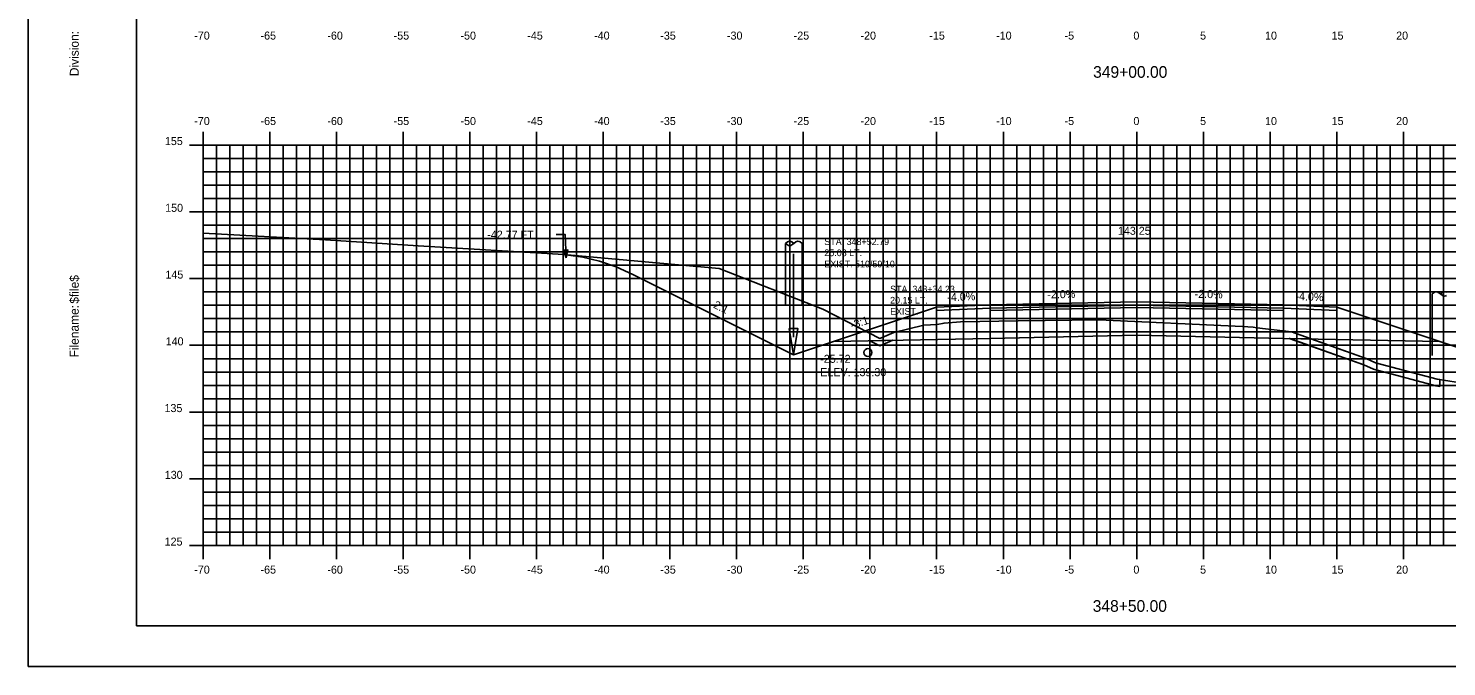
# Model space of a CAD drawing. Extents: x 1144307 to 1144477, y 608981 to 609091.
# Drawn here: x 1144307 to 1144413.3, y 608981.3 to 609029.1 of the extents above; entities that cross this region are included whole.
import ezdxf

# ---------------------------------------------------------------- set-up
doc = ezdxf.new("R2010")
doc.units = 0
for name, color, linetype in [('ANNOTATION', 7, 'Continuous'), ('BORDER', 7, 'Continuous'), ('D_Drainage_Ditch_Line', 7, 'Continuous'), ('D_Roadway_Centerline', 7, 'Continuous'), ('D_Roadway_Centerline_Text', 7, 'Continuous'), ('D_Roadway_Edge_Shoulder', 7, 'Continuous'), ('D_Roadway_Edge_TW', 7, 'Continuous'), ('D_Roadway_Pavement', 7, 'Continuous'), ('D_Roadway_SlopeLines', 7, 'Continuous'), ('D_Roadway_SubGrade', 7, 'Continuous'), ('D_Text_Monospaced', 7, 'Continuous'), ('D_Text_Standard', 7, 'Continuous'), ('H_V ANNOTATION', 7, 'Continuous'), ('MAJOR', 7, 'Continuous'), ('MINOR', 7, 'Continuous'), ('PLOT BOUNDARY', 7, 'Continuous'), ('S_Drainage_Invert', 7, 'Continuous'), ('S_Roadway_Centerline', 7, 'Continuous'), ('S_Utilities_Pole_Power', 7, 'Continuous'), ('SHADING', 7, 'Continuous')]:
    doc.layers.add(name, color=color, linetype=linetype)

msp = doc.modelspace()

# ---------------------------------------------------------------- linework, layer by layer
msp.add_lwpolyline([(1144347.33, 609012.13), (1144348.58, 609011.95), (1144349.83, 609011.65), (1144351.08, 609011.22), (1144352.33, 609010.65), (1144364.38, 609004.63), (1144367.38, 609005.63), (1144375.1, 609008.2), (1144375.11, 609008.2), (1144379.11, 609008.37), (1144390.11, 609008.59), (1144401.11, 609008.37), (1144405.11, 609008.2), (1144412.83, 609005.63), (1144415.83, 609004.63), (1144425.95, 609001.26)])
at = {"layer": 'BORDER'}
msp.add_lwpolyline([(1144315.11, 608984.34), (1144475.11, 608984.34), (1144475.11, 609089.34), (1144315.11, 609089.34)], close=True, dxfattribs=at)
at = {"layer": 'D_Drainage_Ditch_Line'}
msp.add_line((1144364.38, 609005.94), (1144364.38, 609012.19), dxfattribs=at)
msp.add_lwpolyline([(1144364.05, 609006.6), (1144364.71, 609006.6), (1144364.38, 609004.63)], close=True, dxfattribs=at)
at = {"layer": 'D_Roadway_Edge_Shoulder'}
for points in [[(1144379.11, 609008.37), (1144375.11, 609008.2), (1144375.11, 609007.96), (1144379.11, 609008.12)], [(1144401.11, 609008.37), (1144405.11, 609008.2), (1144405.11, 609007.96), (1144401.11, 609008.12)]]:
    msp.add_lwpolyline(points, close=True, dxfattribs=at)
at = {"layer": 'D_Roadway_Edge_TW'}
msp.add_lwpolyline([(1144379.11, 609008.12), (1144379.11, 609008.37), (1144390.11, 609008.59), (1144401.11, 609008.37), (1144401.11, 609008.12), (1144390.11, 609008.34)], close=True, dxfattribs=at)
at = {"layer": 'D_Roadway_Pavement'}
msp.add_lwpolyline([(1144379.11, 609007.95), (1144379.11, 609008.12), (1144390.11, 609008.34), (1144401.11, 609008.12), (1144401.11, 609007.95), (1144390.11, 609008.17)], close=True, dxfattribs=at)
at = {"layer": 'D_Roadway_SlopeLines'}
for points in [[(1144364.38, 609004.63), (1144352.33, 609010.65), (1144351.08, 609011.22), (1144349.83, 609011.65), (1144348.58, 609011.95), (1144347.33, 609012.13)], [(1144367.38, 609005.63), (1144364.38, 609004.63)], [(1144412.83, 609005.63), (1144415.83, 609004.63)]]:
    msp.add_lwpolyline(points, dxfattribs=at)
at = {"layer": 'D_Roadway_SubGrade'}
msp.add_line((1144412.83, 609002.77), (1144412.83, 609002.26), dxfattribs=at)
for points in [[(1144379.11, 609007.95), (1144379.11, 609008.12), (1144375.11, 609007.96), (1144375.11, 609008.2), (1144375.1, 609008.2), (1144367.38, 609005.63), (1144379.11, 609005.86)], [(1144379.11, 609005.86), (1144379.11, 609007.95), (1144390.11, 609008.17), (1144401.11, 609007.95), (1144401.11, 609005.86), (1144390.11, 609006.09)], [(1144401.11, 609007.95), (1144401.11, 609008.12), (1144405.11, 609007.96), (1144405.11, 609008.2), (1144405.11, 609008.2), (1144412.83, 609005.63), (1144401.11, 609005.86)]]:
    msp.add_lwpolyline(points, close=True, dxfattribs=at)
for points in [[(1144370.1, 609005.68), (1144370.84, 609005.31), (1144371.83, 609005.72)], [(1144401.55, 609005.86), (1144401.6, 609005.85), (1144407.13, 609003.89), (1144407.85, 609003.55), (1144412.54, 609002.31), (1144412.83, 609002.26)], [(1144401.55, 609005.86), (1144401.6, 609005.85), (1144407.13, 609003.89), (1144407.85, 609003.55), (1144412.54, 609002.31), (1144412.83, 609002.26)]]:
    msp.add_lwpolyline(points, dxfattribs=at)
at = {"layer": 'D_Text_Standard'}
msp.add_lwpolyline([(1144347.33, 609011.9), (1144347.27, 609013.63), (1144346.59, 609013.63)], dxfattribs=at)
msp.add_lwpolyline([(1144347.33, 609011.9), (1144347.17, 609012.48), (1144347.46, 609012.49)], close=True, dxfattribs=at)
at = {"layer": 'MAJOR'}
for p, q in [((1144320.11, 609021.34), (1144320.11, 609020.34)), ((1144325.11, 609021.34), (1144325.11, 609020.34)), ((1144330.11, 609021.34), (1144330.11, 609020.34)), ((1144335.11, 609021.34), (1144335.11, 609020.34)), ((1144340.11, 609021.34), (1144340.11, 609020.34)), ((1144345.11, 609021.34), (1144345.11, 609020.34)), ((1144350.11, 609021.34), (1144350.11, 609020.34)), ((1144355.11, 609021.34), (1144355.11, 609020.34)), ((1144360.11, 609021.34), (1144360.11, 609020.34)), ((1144365.11, 609021.34), (1144365.11, 609020.34)), ((1144370.11, 609021.34), (1144370.11, 609020.34)), ((1144375.11, 609021.34), (1144375.11, 609020.34)), ((1144380.11, 609021.34), (1144380.11, 609020.34)), ((1144385.11, 609021.34), (1144385.11, 609020.34)), ((1144390.11, 609021.34), (1144390.11, 609020.34)), ((1144395.11, 609021.34), (1144395.11, 609020.34)), ((1144400.11, 609021.34), (1144400.11, 609020.34)), ((1144405.11, 609021.34), (1144405.11, 609020.34)), ((1144410.11, 609021.34), (1144410.11, 609020.34)), ((1144319.1, 609020.34), (1144320.11, 609020.34)), ((1144320.11, 609020.34), (1144460.11, 609020.34)), ((1144320.11, 608990.34), (1144320.11, 609020.34)), ((1144320.11, 608990.34), (1144320.11, 609020.34)), ((1144320.11, 609020.34), (1144460.11, 609020.34)), ((1144325.11, 608990.34), (1144325.11, 609020.34)), ((1144330.11, 608990.34), (1144330.11, 609020.34)), ((1144335.11, 608990.34), (1144335.11, 609020.34)), ((1144340.11, 608990.34), (1144340.11, 609020.34)), ((1144345.11, 608990.34), (1144345.11, 609020.34)), ((1144350.11, 608990.34), (1144350.11, 609020.34)), ((1144355.11, 608990.34), (1144355.11, 609020.34)), ((1144360.11, 608990.34), (1144360.11, 609020.34)), ((1144365.11, 608990.34), (1144365.11, 609020.34)), ((1144370.11, 608990.34), (1144370.11, 609020.34)), ((1144375.11, 608990.34), (1144375.11, 609020.34)), ((1144380.11, 608990.34), (1144380.11, 609020.34)), ((1144385.11, 608990.34), (1144385.11, 609020.34)), ((1144390.11, 608990.34), (1144390.11, 609020.34)), ((1144395.11, 608990.34), (1144395.11, 609020.34)), ((1144400.11, 608990.34), (1144400.11, 609020.34)), ((1144405.11, 608990.34), (1144405.11, 609020.34)), ((1144410.11, 608990.34), (1144410.11, 609020.34)), ((1144319.1, 609015.34), (1144320.11, 609015.34)), ((1144320.11, 609015.34), (1144460.11, 609015.34)), ((1144319.1, 609010.34), (1144320.11, 609010.34)), ((1144320.11, 609010.34), (1144460.11, 609010.34)), ((1144319.1, 609005.34), (1144320.11, 609005.34)), ((1144320.11, 609005.34), (1144460.11, 609005.34)), ((1144319.1, 609000.34), (1144320.11, 609000.34)), ((1144320.11, 609000.34), (1144460.11, 609000.34)), ((1144319.1, 608995.34), (1144320.11, 608995.34)), ((1144320.11, 608995.34), (1144460.11, 608995.34)), ((1144319.1, 608990.34), (1144320.11, 608990.34)), ((1144320.11, 608990.34), (1144460.11, 608990.34)), ((1144320.11, 608990.34), (1144460.11, 608990.34)), ((1144320.11, 608989.33), (1144320.11, 608990.34)), ((1144325.11, 608989.33), (1144325.11, 608990.34)), ((1144330.11, 608989.33), (1144330.11, 608990.34)), ((1144335.11, 608989.33), (1144335.11, 608990.34)), ((1144340.11, 608989.33), (1144340.11, 608990.34)), ((1144345.11, 608989.33), (1144345.11, 608990.34)), ((1144350.11, 608989.33), (1144350.11, 608990.34)), ((1144355.11, 608989.33), (1144355.11, 608990.34)), ((1144360.11, 608989.33), (1144360.11, 608990.34)), ((1144365.11, 608989.33), (1144365.11, 608990.34)), ((1144370.11, 608989.33), (1144370.11, 608990.34)), ((1144375.11, 608989.33), (1144375.11, 608990.34)), ((1144380.11, 608989.33), (1144380.11, 608990.34)), ((1144385.11, 608989.33), (1144385.11, 608990.34)), ((1144390.11, 608989.33), (1144390.11, 608990.34)), ((1144395.11, 608989.33), (1144395.11, 608990.34)), ((1144400.11, 608989.33), (1144400.11, 608990.34)), ((1144405.11, 608989.33), (1144405.11, 608990.34)), ((1144410.11, 608989.33), (1144410.11, 608990.34))]:
    msp.add_line(p, q, dxfattribs=at)
at = {"layer": 'MINOR'}
for p, q in [((1144321.11, 608990.34), (1144321.11, 609020.34)), ((1144322.11, 608990.34), (1144322.11, 609020.34)), ((1144323.11, 608990.34), (1144323.11, 609020.34)), ((1144324.11, 608990.34), (1144324.11, 609020.34)), ((1144326.11, 608990.34), (1144326.11, 609020.34)), ((1144327.11, 608990.34), (1144327.11, 609020.34)), ((1144328.11, 608990.34), (1144328.11, 609020.34)), ((1144329.11, 608990.34), (1144329.11, 609020.34)), ((1144331.11, 608990.34), (1144331.11, 609020.34)), ((1144332.11, 608990.34), (1144332.11, 609020.34)), ((1144333.11, 608990.34), (1144333.11, 609020.34)), ((1144334.11, 608990.34), (1144334.11, 609020.34)), ((1144336.11, 608990.34), (1144336.11, 609020.34)), ((1144337.11, 608990.34), (1144337.11, 609020.34)), ((1144338.11, 608990.34), (1144338.11, 609020.34)), ((1144339.11, 608990.34), (1144339.11, 609020.34)), ((1144341.11, 608990.34), (1144341.11, 609020.34)), ((1144342.11, 608990.34), (1144342.11, 609020.34)), ((1144343.11, 608990.34), (1144343.11, 609020.34)), ((1144344.11, 608990.34), (1144344.11, 609020.34)), ((1144346.11, 608990.34), (1144346.11, 609020.34)), ((1144347.11, 608990.34), (1144347.11, 609020.34)), ((1144348.11, 608990.34), (1144348.11, 609020.34)), ((1144349.11, 608990.34), (1144349.11, 609020.34)), ((1144351.11, 608990.34), (1144351.11, 609020.34)), ((1144352.11, 608990.34), (1144352.11, 609020.34)), ((1144353.11, 608990.34), (1144353.11, 609020.34)), ((1144354.11, 608990.34), (1144354.11, 609020.34)), ((1144356.11, 608990.34), (1144356.11, 609020.34)), ((1144357.11, 608990.34), (1144357.11, 609020.34)), ((1144358.11, 608990.34), (1144358.11, 609020.34)), ((1144359.11, 608990.34), (1144359.11, 609020.34)), ((1144361.11, 608990.34), (1144361.11, 609020.34)), ((1144362.11, 608990.34), (1144362.11, 609020.34)), ((1144363.11, 608990.34), (1144363.11, 609020.34)), ((1144364.11, 608990.34), (1144364.11, 609020.34)), ((1144366.11, 608990.34), (1144366.11, 609020.34)), ((1144367.11, 608990.34), (1144367.11, 609020.34)), ((1144368.11, 608990.34), (1144368.11, 609020.34)), ((1144369.11, 608990.34), (1144369.11, 609020.34)), ((1144371.11, 608990.34), (1144371.11, 609020.34)), ((1144372.11, 608990.34), (1144372.11, 609020.34)), ((1144373.11, 608990.34), (1144373.11, 609020.34)), ((1144374.11, 608990.34), (1144374.11, 609020.34)), ((1144376.11, 608990.34), (1144376.11, 609020.34)), ((1144377.11, 608990.34), (1144377.11, 609020.34)), ((1144378.11, 608990.34), (1144378.11, 609020.34)), ((1144379.11, 608990.34), (1144379.11, 609020.34)), ((1144381.11, 608990.34), (1144381.11, 609020.34)), ((1144382.11, 608990.34), (1144382.11, 609020.34)), ((1144383.11, 608990.34), (1144383.11, 609020.34)), ((1144384.11, 608990.34), (1144384.11, 609020.34)), ((1144386.11, 608990.34), (1144386.11, 609020.34)), ((1144387.11, 608990.34), (1144387.11, 609020.34)), ((1144388.11, 608990.34), (1144388.11, 609020.34)), ((1144389.11, 608990.34), (1144389.11, 609020.34)), ((1144391.11, 608990.34), (1144391.11, 609020.34)), ((1144392.11, 608990.34), (1144392.11, 609020.34)), ((1144393.11, 608990.34), (1144393.11, 609020.34)), ((1144394.11, 608990.34), (1144394.11, 609020.34)), ((1144396.11, 608990.34), (1144396.11, 609020.34)), ((1144397.11, 608990.34), (1144397.11, 609020.34)), ((1144398.11, 608990.34), (1144398.11, 609020.34)), ((1144399.11, 608990.34), (1144399.11, 609020.34)), ((1144401.11, 608990.34), (1144401.11, 609020.34)), ((1144402.11, 608990.34), (1144402.11, 609020.34)), ((1144403.11, 608990.34), (1144403.11, 609020.34)), ((1144404.11, 608990.34), (1144404.11, 609020.34)), ((1144406.11, 608990.34), (1144406.11, 609020.34)), ((1144407.11, 608990.34), (1144407.11, 609020.34)), ((1144408.11, 608990.34), (1144408.11, 609020.34)), ((1144409.11, 608990.34), (1144409.11, 609020.34)), ((1144411.11, 608990.34), (1144411.11, 609020.34)), ((1144412.11, 608990.34), (1144412.11, 609020.34)), ((1144413.11, 608990.34), (1144413.11, 609020.34)), ((1144320.11, 609019.34), (1144460.11, 609019.34)), ((1144320.11, 609019.34), (1144321.11, 609019.34)), ((1144320.11, 609018.34), (1144460.11, 609018.34)), ((1144320.11, 609018.34), (1144321.11, 609018.34)), ((1144320.11, 609017.34), (1144460.11, 609017.34)), ((1144320.11, 609017.34), (1144321.11, 609017.34)), ((1144320.11, 609016.34), (1144460.11, 609016.34)), ((1144320.11, 609016.34), (1144321.11, 609016.34)), ((1144320.11, 609014.34), (1144460.11, 609014.34)), ((1144320.11, 609014.34), (1144321.11, 609014.34)), ((1144320.11, 609013.34), (1144460.11, 609013.34)), ((1144320.11, 609013.34), (1144321.11, 609013.34)), ((1144320.11, 609012.34), (1144460.11, 609012.34)), ((1144320.11, 609012.34), (1144321.11, 609012.34)), ((1144320.11, 609011.34), (1144460.11, 609011.34)), ((1144320.11, 609011.34), (1144321.11, 609011.34)), ((1144320.11, 609009.34), (1144460.11, 609009.34)), ((1144320.11, 609009.34), (1144321.11, 609009.34)), ((1144320.11, 609008.34), (1144460.11, 609008.34)), ((1144320.11, 609008.34), (1144321.11, 609008.34)), ((1144320.11, 609007.34), (1144460.11, 609007.34)), ((1144320.11, 609007.34), (1144321.11, 609007.34)), ((1144320.11, 609006.34), (1144460.11, 609006.34)), ((1144320.11, 609006.34), (1144321.11, 609006.34)), ((1144320.11, 609004.34), (1144460.11, 609004.34)), ((1144320.11, 609004.34), (1144321.11, 609004.34)), ((1144320.11, 609003.34), (1144460.11, 609003.34)), ((1144320.11, 609003.34), (1144321.11, 609003.34)), ((1144320.11, 609002.34), (1144460.11, 609002.34)), ((1144320.11, 609002.34), (1144321.11, 609002.34)), ((1144320.11, 609001.34), (1144460.11, 609001.34)), ((1144320.11, 609001.34), (1144321.11, 609001.34)), ((1144320.11, 608999.34), (1144460.11, 608999.34)), ((1144320.11, 608999.34), (1144321.11, 608999.34)), ((1144320.11, 608998.34), (1144460.11, 608998.34)), ((1144320.11, 608998.34), (1144321.11, 608998.34)), ((1144320.11, 608997.34), (1144460.11, 608997.34)), ((1144320.11, 608997.34), (1144321.11, 608997.34)), ((1144320.11, 608996.34), (1144460.11, 608996.34)), ((1144320.11, 608996.34), (1144321.11, 608996.34)), ((1144320.11, 608994.34), (1144460.11, 608994.34)), ((1144320.11, 608994.34), (1144321.11, 608994.34)), ((1144320.11, 608993.34), (1144460.11, 608993.34)), ((1144320.11, 608993.34), (1144321.11, 608993.34)), ((1144320.11, 608992.34), (1144460.11, 608992.34)), ((1144320.11, 608992.34), (1144321.11, 608992.34)), ((1144320.11, 608991.34), (1144460.11, 608991.34)), ((1144320.11, 608991.34), (1144321.11, 608991.34))]:
    msp.add_line(p, q, dxfattribs=at)
at = {"layer": 'PLOT BOUNDARY'}
msp.add_lwpolyline([(1144307.01, 608981.28), (1144477.01, 608981.28), (1144477.01, 609091.28), (1144307.01, 609091.28)], close=True, dxfattribs=at)
at = {"layer": 'S_Drainage_Invert'}
msp.add_circle((1144369.96, 609004.8), 0.3, dxfattribs=at)
at = {"layer": 'S_Roadway_Centerline'}
msp.add_lwpolyline([(1144320.11, 609013.74), (1144329.3, 609013.24), (1144336.24, 609012.79), (1144347.17, 609012.14), (1144358.81, 609011.09), (1144366.57, 609008.06), (1144370.86, 609005.86), (1144371.9, 609006.29), (1144374.14, 609006.84), (1144375.16, 609006.91), (1144375.67, 609007.01), (1144376.9, 609007.1), (1144381.21, 609007.17), (1144387.28, 609007.24), (1144398.04, 609006.75), (1144398.83, 609006.71), (1144399.11, 609006.66), (1144401.71, 609006.34), (1144407.32, 609004.35), (1144408.02, 609004.03), (1144412.64, 609002.8), (1144421.53, 609001.41)], dxfattribs=at)
at = {"layer": 'S_Utilities_Pole_Power'}
for p, q in [((1144363.77, 609012.97), (1144363.93, 609013.08)), ((1144363.77, 609008.35), (1144363.78, 609012.97)), ((1144363.93, 609012.86), (1144363.77, 609012.97)), ((1144364.24, 609013.08), (1144364.4, 609012.97)), ((1144364.4, 609012.97), (1144364.24, 609012.86)), ((1144364.56, 609013.08), (1144364.4, 609012.97)), ((1144365.02, 609012.97), (1144364.87, 609013.08)), ((1144365.02, 609008.35), (1144365.03, 609012.97)), ((1144412.25, 609009.19), (1144412.41, 609009.3)), ((1144412.72, 609009.3), (1144412.88, 609009.19)), ((1144413.03, 609009.3), (1144412.88, 609009.19)), ((1144412.25, 609004.57), (1144412.25, 609009.19)), ((1144412.88, 609009.19), (1144413.03, 609009.08))]:
    msp.add_line(p, q, dxfattribs=at)
for centre, start, end in [((1144364.09, 609012.86), 90, 125.2644), ((1144364.09, 609013.08), 234.7356, 270), ((1144364.09, 609012.86), 54.7356, 90), ((1144364.09, 609013.08), 270, 305.2644), ((1144364.71, 609012.86), 90, 125.2644), ((1144364.71, 609012.86), 54.7356, 90), ((1144412.56, 609009.08), 90, 125.2644), ((1144412.56, 609009.08), 54.7356, 90), ((1144413.19, 609009.08), 90, 125.2644), ((1144413.19, 609009.08), 54.7356, 90), ((1144413.19, 609009.3), 234.7356, 270), ((1144413.19, 609009.3), 270, 305.2644)]:
    msp.add_arc(centre, 0.271, start, end, dxfattribs=at)
at = {"layer": 'SHADING'}
for p, q in [((1144371.83, 609005.72), (1144370.1, 609005.68)), ((1144401.55, 609005.86), (1144407.13, 609003.89)), ((1144403.17, 609005.82), (1144401.55, 609005.86)), ((1144407.13, 609003.89), (1144407.85, 609003.55)), ((1144407.85, 609003.55), (1144412.54, 609002.31)), ((1144412.54, 609002.31), (1144412.83, 609002.26)), ((1144412.83, 609002.26), (1144412.83, 609002.77))]:
    msp.add_line(p, q, dxfattribs=at)
for points in [[(1144370.1, 609005.68), (1144370.84, 609005.31), (1144371.83, 609005.72)], [(1144412.83, 609002.77), (1144412.64, 609002.8), (1144408.02, 609004.03), (1144407.32, 609004.35), (1144403.17, 609005.82)]]:
    msp.add_lwpolyline(points, dxfattribs=at)

# ---------------------------------------------------------------- texts
at = {"layer": 'ANNOTATION'}
for s, rotation, p in [('-4.0%', 2.2906, (1144375.92, 609008.64)), ('-2.0%', 1.1458, (1144383.41, 609008.85)), ('-2.0%', 358.8542, (1144394.45, 609008.9)), ('-4.0%', 357.7094, (1144402, 609008.73)), ('2:1', 333.4349, (1144358.32, 609008.18)), ('-3:1', 18.4348, (1144368.76, 609006.54))]:
    msp.add_text(s, height=0.6, rotation=rotation, dxfattribs=at).set_placement(p)
at = {"layer": 'BORDER'}
for s, p in [('Division:', (1144310.79, 609025.5)), ('$file$', (1144310.79, 609008.46)), ('Filename:', (1144310.79, 609004.43))]:
    msp.add_text(s, height=0.67, rotation=90, dxfattribs=at).set_placement(p)
at = {"layer": 'D_Roadway_Centerline'}
for s, p in [('C', (1144390.1, 609008.59)), ('L', (1144390.11, 609008.58))]:
    msp.add_text(s, height=0.0146, dxfattribs=at).set_placement(p)
at = {"layer": 'D_Roadway_Centerline_Text'}
msp.add_text('143.25', height=0.6, dxfattribs=at).set_placement((1144388.7, 609013.62))
at = {"layer": 'D_Text_Monospaced'}
for s, p in [('STA. 348+52.79', (1144366.69, 609012.85)), ('25.08 LT.', (1144366.69, 609012.02)), ('EXIST. 510/59/10', (1144366.69, 609011.18)), ('STA. 348+34.23', (1144371.62, 609009.3)), ('20.15 LT.', (1144371.62, 609008.47)), ('EXIST. ', (1144371.62, 609007.63))]:
    msp.add_text(s, height=0.5, dxfattribs=at).set_placement(p)
at = {"layer": 'D_Text_Standard'}
for s, p in [('-42.77 FT', (1144341.42, 609013.33)), ('-25.72', (1144366.38, 609004.03)), ('ELEV. 139.30', (1144366.38, 609003.03))]:
    msp.add_text(s, height=0.6, dxfattribs=at).set_placement(p)
at = {"layer": 'H_V ANNOTATION'}
for s, height, p in [('-70', 0.6, (1144319.45, 609028.24)), ('-65', 0.6, (1144324.42, 609028.24)), ('-60', 0.6, (1144329.43, 609028.24)), ('-55', 0.6, (1144334.4, 609028.24)), ('-50', 0.6, (1144339.41, 609028.24)), ('-45', 0.6, (1144344.42, 609028.24)), ('-40', 0.6, (1144349.43, 609028.24)), ('-35', 0.6, (1144354.39, 609028.24)), ('-30', 0.6, (1144359.39, 609028.24)), ('-25', 0.6, (1144364.39, 609028.24)), ('-20', 0.6, (1144369.4, 609028.24)), ('-15', 0.6, (1144374.56, 609028.24)), ('-10', 0.6, (1144379.57, 609028.24)), ('-5', 0.6, (1144384.7, 609028.24)), ('0', 0.6, (1144389.86, 609028.24)), ('5', 0.6, (1144394.86, 609028.24)), ('10', 0.6, (1144399.73, 609028.24)), ('15', 0.6, (1144404.72, 609028.24)), ('20', 0.6, (1144409.56, 609028.24)), ('349+00.00', 0.875, (1144386.84, 609025.38)), ('-70', 0.6, (1144319.45, 609021.84)), ('-65', 0.6, (1144324.42, 609021.84)), ('-60', 0.6, (1144329.43, 609021.84)), ('-55', 0.6, (1144334.4, 609021.84)), ('-50', 0.6, (1144339.41, 609021.84)), ('-45', 0.6, (1144344.42, 609021.84)), ('-40', 0.6, (1144349.43, 609021.84)), ('-35', 0.6, (1144354.39, 609021.84)), ('-30', 0.6, (1144359.39, 609021.84)), ('-25', 0.6, (1144364.39, 609021.84)), ('-20', 0.6, (1144369.4, 609021.84)), ('-15', 0.6, (1144374.56, 609021.84)), ('-10', 0.6, (1144379.57, 609021.84)), ('-5', 0.6, (1144384.7, 609021.84)), ('0', 0.6, (1144389.86, 609021.84)), ('5', 0.6, (1144394.86, 609021.84)), ('10', 0.6, (1144399.73, 609021.84)), ('15', 0.6, (1144404.72, 609021.84)), ('20', 0.6, (1144409.56, 609021.84)), ('155', 0.6, (1144317.25, 609020.34)), ('150', 0.6, (1144317.27, 609015.34)), ('145', 0.6, (1144317.29, 609010.34)), ('140', 0.6, (1144317.31, 609005.34)), ('135', 0.6, (1144317.22, 609000.34)), ('130', 0.6, (1144317.24, 608995.34)), ('125', 0.6, (1144317.23, 608990.34)), ('-70', 0.6, (1144319.45, 608988.24)), ('-65', 0.6, (1144324.42, 608988.24)), ('-60', 0.6, (1144329.43, 608988.24)), ('-55', 0.6, (1144334.4, 608988.24)), ('-50', 0.6, (1144339.41, 608988.24)), ('-45', 0.6, (1144344.42, 608988.24)), ('-40', 0.6, (1144349.43, 608988.24)), ('-35', 0.6, (1144354.39, 608988.24)), ('-30', 0.6, (1144359.39, 608988.24)), ('-25', 0.6, (1144364.39, 608988.24)), ('-20', 0.6, (1144369.4, 608988.24)), ('-15', 0.6, (1144374.56, 608988.24)), ('-10', 0.6, (1144379.57, 608988.24)), ('-5', 0.6, (1144384.7, 608988.24)), ('0', 0.6, (1144389.86, 608988.24)), ('5', 0.6, (1144394.86, 608988.24)), ('10', 0.6, (1144399.73, 608988.24)), ('15', 0.6, (1144404.72, 608988.24)), ('20', 0.6, (1144409.56, 608988.24)), ('348+50.00', 0.875, (1144386.81, 608985.38))]:
    msp.add_text(s, height=height, dxfattribs=at).set_placement(p)
at = {"layer": 'MAJOR'}
msp.add_text('-', height=0.006, dxfattribs=at).set_placement((1144320.1, 608990.34))
at = {"layer": 'S_Roadway_Centerline'}
for s, p in [('C', (1144387.27, 609007.24)), ('L', (1144387.27, 609007.23))]:
    msp.add_text(s, height=0.0146, dxfattribs=at).set_placement(p)

doc.saveas('drawing.dxf')
